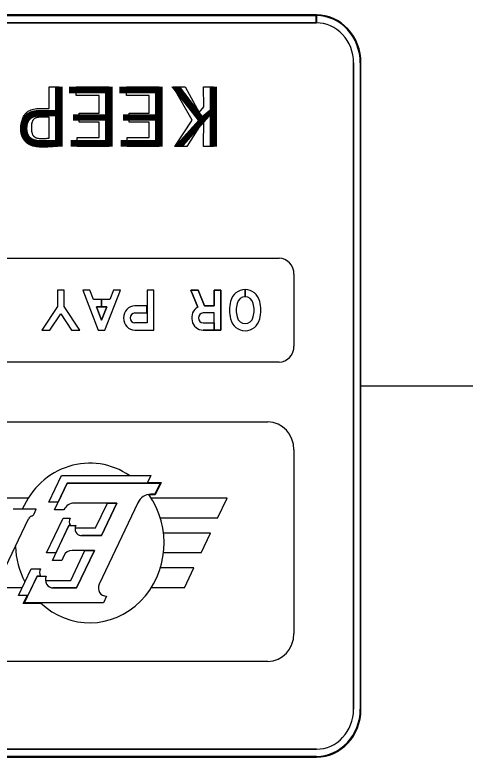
# Model space of a CAD drawing. Extents: x -102643 to -98250, y 54554 to 62384.
# Drawn here: x -101344 to -101029, y 61400 to 61919 of the extents above; entities that cross this region are included whole.
import ezdxf

# ---------------------------------------------------------------- set-up
doc = ezdxf.new("R2010")
doc.units = 0
for name, color, linetype in [('GSBWFill', 7, 'Continuous'), ('GSColorFill', 7, 'Continuous'), ('GSOutline', 7, 'Continuous'), ('LeaderLine_dp', 7, 'Continuous'), ('SignPanel', 7, 'Continuous')]:
    doc.layers.add(name, color=color, linetype=linetype)

msp = doc.modelspace()

# ---------------------------------------------------------------- linework, layer by layer
at = {"layer": 'GSBWFill'}
for p, q in [((-101133.26, 61919), (-101585.67, 61919)), ((-101133.26, 61913.42), (-101133.26, 61919)), ((-101133.21, 61919), (-101133.21, 61913.42)), ((-101585.67, 61913.42), (-101133.26, 61913.42)), ((-101107.2, 61885.49), (-101107.2, 61433.02)), ((-101102, 61433.02), (-101102, 61885.49)), ((-101133.21, 61405.09), (-101585.67, 61405.09)), ((-101585.67, 61399.51), (-101133.21, 61399.51))]:
    msp.add_line(p, q, dxfattribs=at)
for centre, major_axis, start_param, end_param in [((-101133.21, 61885.49), (0, -33.52), 1.570796, 3.141593), ((-101133.21, 61885.49), (0, -27.93), 1.570796, 3.141593), ((-101133.21, 61433.02), (0, -33.52), 0, 1.570796), ((-101133.21, 61433.02), (0, -27.93), 0, 1.570796)]:
    msp.add_ellipse(centre, major_axis=major_axis, ratio=0.931035, start_param=start_param, end_param=end_param, dxfattribs=at)
at = {"layer": 'GSColorFill'}
for p, q in [((-101133.21, 61919), (-101585.67, 61919)), ((-101102, 61433.02), (-101102, 61885.49)), ((-101585.67, 61399.51), (-101133.21, 61399.51))]:
    msp.add_line(p, q, dxfattribs=at)
for centre, start_param, end_param in [((-101133.21, 61885.49), 1.570796, 3.141593), ((-101133.21, 61433.02), 0, 1.570796)]:
    msp.add_ellipse(centre, major_axis=(0, -33.52), ratio=0.931035, start_param=start_param, end_param=end_param, dxfattribs=at)
at = {"layer": 'GSOutline'}
for p, q in [((-101133.21, 61919), (-101585.67, 61919)), ((-101133.21, 61913.42), (-101585.67, 61913.42)), ((-101107.2, 61433.02), (-101107.2, 61885.49)), ((-101102, 61433.02), (-101102, 61885.49)), ((-101585.67, 61405.09), (-101133.21, 61405.09)), ((-101585.67, 61399.51), (-101133.21, 61399.51))]:
    msp.add_line(p, q, dxfattribs=at)
for centre, major_axis, start_param, end_param in [((-101133.21, 61885.49), (0, -33.52), 1.570796, 3.141593), ((-101133.21, 61885.49), (0, -27.93), 1.570796, 3.141593), ((-101133.21, 61433.02), (0, -33.52), 0, 1.570796), ((-101133.21, 61433.02), (0, -27.93), 0, 1.570796)]:
    msp.add_ellipse(centre, major_axis=major_axis, ratio=0.931035, start_param=start_param, end_param=end_param, dxfattribs=at)
at = {"layer": 'LeaderLine_dp'}
msp.add_line((-101102, 61659.26), (-100943.43, 61659.26), dxfattribs=at)
at = {"layer": 'SignPanel'}
for p, q in [((-101133.26, 61919), (-101585.67, 61919)), ((-101133.21, 61919), (-101585.67, 61919)), ((-101133.26, 61913.42), (-101133.26, 61919)), ((-101133.21, 61919), (-101133.21, 61913.42)), ((-101133.21, 61919), (-101133.21, 61918.45)), ((-101133.21, 61918.45), (-101133.21, 61919)), ((-101585.67, 61918.45), (-101133.21, 61918.45)), ((-101585.67, 61913.42), (-101133.26, 61913.42)), ((-101107.2, 61885.49), (-101107.2, 61433.02)), ((-101102.52, 61885.49), (-101102.52, 61433.02)), ((-101102, 61433.02), (-101102, 61885.49)), ((-101102, 61433.02), (-101102, 61885.49)), ((-101559.62, 61748.63), (-101159.26, 61748.63)), ((-101148.86, 61737.46), (-101148.86, 61687.19)), ((-101183.01, 61726.78), (-101183.01, 61721.75)), ((-101183.01, 61726.78), (-101183.01, 61721.75)), ((-101183, 61721.75), (-101183, 61726.78)), ((-101183, 61721.75), (-101183, 61726.78)), ((-101251.65, 61715.4), (-101260.11, 61715.4)), ((-101251.65, 61703.39), (-101260.11, 61703.39)), ((-101251.65, 61703.39), (-101260.11, 61703.39)), ((-101251.65, 61703.39), (-101260.11, 61703.39)), ((-101159.26, 61676.01), (-101559.62, 61676.01)), ((-101551.82, 61634.08), (-101167.06, 61634.08)), ((-101148.86, 61614.53), (-101148.86, 61486.09)), ((-101320.37, 61577.85), (-101311.51, 61596.52)), ((-101311.51, 61596.52), (-101248.95, 61596.52)), ((-101248.95, 61596.52), (-101251.42, 61591.28)), ((-101251.21, 61591.74), (-101241.75, 61591.74)), ((-101241.75, 61591.74), (-101245.87, 61583.05)), ((-101316.29, 61572.62), (-101307.44, 61591.28)), ((-101307.44, 61591.28), (-101313.8, 61577.85)), ((-101307.44, 61591.28), (-101242.45, 61591.28)), ((-101251.42, 61591.28), (-101307.44, 61591.28)), ((-101242.45, 61591.28), (-101246.14, 61583.5)), ((-101246.14, 61583.5), (-101248.86, 61583.5)), ((-101245.87, 61583.05), (-101248.86, 61583.05)), ((-101334.71, 61580.81), (-101494.59, 61580.81)), ((-101313.8, 61577.85), (-101320.37, 61577.85)), ((-101272.75, 61577.31), (-101302.58, 61577.31)), ((-101287.6, 61559.88), (-101279.32, 61577.31)), ((-101258.12, 61577.41), (-101285.1, 61520.55)), ((-101283.52, 61554.63), (-101272.75, 61577.31)), ((-101272.75, 61577.31), (-101283.52, 61554.63)), ((-101279.32, 61577.31), (-101272.75, 61577.31)), ((-101195.66, 61580.81), (-101248.73, 61580.81)), ((-101202.27, 61566.84), (-101195.66, 61580.81)), ((-101329.09, 61572.96), (-101345.34, 61572.96)), ((-101330.55, 61569.88), (-101329.09, 61572.96)), ((-101309.78, 61572.62), (-101316.29, 61572.62)), ((-101350.6, 61532.43), (-101334.5, 61566.35)), ((-101321.91, 61542.41), (-101310.32, 61566.84)), ((-101310.32, 61566.84), (-101305.44, 61566.84)), ((-101202.27, 61566.84), (-101242.33, 61566.84)), ((-101317.82, 61537.17), (-101306.24, 61561.61)), ((-101306.24, 61561.61), (-101315.34, 61542.41)), ((-101306.24, 61561.61), (-101301.34, 61561.61)), ((-101305.21, 61561.61), (-101306.24, 61561.61)), ((-101301.94, 61559.93), (-101287.6, 61559.88)), ((-101207.23, 61556.37), (-101240.13, 61556.37)), ((-101213.85, 61542.41), (-101207.23, 61556.37)), ((-101297.78, 61554.63), (-101283.52, 61554.63)), ((-101283.52, 61554.63), (-101297.17, 61554.67)), ((-101315.34, 61542.41), (-101321.91, 61542.41)), ((-101309.82, 61540.34), (-101311.32, 61537.17)), ((-101304.98, 61523.21), (-101295.05, 61544.15)), ((-101288.48, 61544.15), (-101304.03, 61544.15)), ((-101300.9, 61517.98), (-101288.48, 61544.15)), ((-101288.48, 61544.15), (-101300.9, 61517.98)), ((-101295.05, 61544.15), (-101288.48, 61544.15)), ((-101213.85, 61542.41), (-101240.13, 61542.41)), ((-101311.32, 61537.17), (-101317.82, 61537.17)), ((-101341.5, 61512.74), (-101332.65, 61531.41)), ((-101332.65, 61531.41), (-101326.16, 61531.41)), ((-101218.81, 61531.94), (-101242.33, 61531.94)), ((-101225.43, 61517.98), (-101218.81, 61531.94)), ((-101337.43, 61507.51), (-101328.58, 61526.17)), ((-101328.56, 61526.19), (-101334.94, 61512.74)), ((-101328.58, 61526.17), (-101322.07, 61526.17)), ((-101326.15, 61526.19), (-101328.56, 61526.19)), ((-101322.66, 61523.21), (-101304.98, 61523.21)), ((-101339.02, 61517.98), (-101524.4, 61517.98)), ((-101317.46, 61517.98), (-101300.9, 61517.98)), ((-101300.9, 61517.98), (-101317.46, 61517.98)), ((-101225.43, 61517.98), (-101248.73, 61517.98)), ((-101334.94, 61512.74), (-101341.5, 61512.74)), ((-101338.21, 61506.99), (-101335.49, 61512.74)), ((-101279.96, 61512.19), (-101282.18, 61507.51)), ((-101325.55, 61506.99), (-101338.21, 61506.99)), ((-101282.18, 61507.51), (-101337.43, 61507.51)), ((-101167.06, 61466.54), (-101551.82, 61466.54)), ((-101133.21, 61405.09), (-101585.67, 61405.09)), ((-101133.21, 61400.07), (-101585.67, 61400.07)), ((-101585.67, 61399.51), (-101133.21, 61399.51)), ((-101585.67, 61399.51), (-101133.21, 61399.51))]:
    msp.add_line(p, q, dxfattribs=at)
for points in [[(-101326.81, 61853.46), (-101320.16, 61853.46), (-101320.16, 61868.73), (-101313.15, 61868.73), (-101313.15, 61827.1)], [(-101278.16, 61868.73), (-101278.16, 61826.83), (-101300.48, 61826.83), (-101300.48, 61833.25), (-101285.18, 61833.25), (-101285.18, 61843.79), (-101299.01, 61843.79), (-101299.01, 61850.25), (-101285.18, 61850.25), (-101285.18, 61862.47), (-101301.08, 61862.47), (-101301.08, 61868.73), (-101278.16, 61868.73)], [(-101243.17, 61868.73), (-101243.17, 61826.83), (-101265.5, 61826.83), (-101265.5, 61833.25), (-101250.19, 61833.25), (-101250.19, 61843.79), (-101264.03, 61843.79), (-101264.03, 61850.25), (-101250.19, 61850.25), (-101250.19, 61862.47), (-101266.09, 61862.47), (-101266.09, 61868.73), (-101243.17, 61868.73)], [(-101224.92, 61868.73), (-101215.12, 61850.63), (-101212, 61854.74), (-101212.08, 61868.73), (-101205.06, 61868.73), (-101205.06, 61826.83), (-101212.08, 61826.83), (-101212, 61845.31), (-101212.24, 61845.31), (-101223.75, 61826.83), (-101232.24, 61826.83), (-101220.05, 61845.23), (-101233.41, 61868.73), (-101224.92, 61868.73)], [(-101320.16, 61832.74), (-101320.16, 61847.4), (-101325.59, 61847.4)], [(-101260.11, 61698.36), (-101246.97, 61698.36), (-101246.97, 61726.29), (-101251.65, 61726.29), (-101251.65, 61715.4)], [(-101260.11, 61698.36), (-101246.97, 61698.36), (-101246.97, 61726.29), (-101251.65, 61726.29), (-101251.65, 61703.39)], [(-101260.11, 61698.36), (-101246.97, 61698.36), (-101246.97, 61726.29), (-101251.65, 61726.29), (-101251.65, 61703.39)], [(-101212.48, 61698.36), (-101199.91, 61698.36), (-101199.91, 61726.29), (-101204.59, 61726.29), (-101204.59, 61715.4), (-101211.48, 61715.4), (-101215.87, 61726.29), (-101220.97, 61726.29), (-101216.18, 61714.41)], [(-101216.18, 61714.41), (-101220.97, 61726.29), (-101215.87, 61726.29), (-101211.48, 61715.4), (-101204.59, 61715.4), (-101204.59, 61726.29), (-101199.91, 61726.29), (-101199.91, 61698.36), (-101204.59, 61698.36), (-101204.59, 61710.37), (-101212.48, 61710.37)], [(-101216.18, 61714.41), (-101220.97, 61726.29), (-101215.87, 61726.29), (-101211.48, 61715.4), (-101204.59, 61715.4), (-101204.59, 61726.29), (-101199.91, 61726.29), (-101199.91, 61698.36), (-101204.59, 61698.36), (-101204.59, 61710.37), (-101212.48, 61710.37)], [(-101260.11, 61710.37), (-101251.66, 61710.37), (-101251.66, 61715.4), (-101260.11, 61715.4)], [(-101260.11, 61710.37), (-101251.66, 61710.37), (-101251.66, 61715.4), (-101260.11, 61715.4)], [(-101260.11, 61710.37), (-101251.65, 61710.37), (-101251.65, 61703.39)], [(-101212.48, 61703.39), (-101204.59, 61703.39), (-101204.59, 61710.37), (-101212.48, 61710.37)], [(-101204.59, 61703.39), (-101204.59, 61698.36), (-101212.48, 61698.36)], [(-101212.48, 61703.39), (-101204.59, 61703.39)], [(-101204.59, 61703.39), (-101204.59, 61698.36), (-101212.48, 61698.36)], [(-101212.48, 61703.39), (-101204.59, 61703.39)]]:
    msp.add_lwpolyline(points, dxfattribs=at)
for points in [[(-101314.32, 61714.98), (-101325.24, 61698.36), (-101319.52, 61698.36), (-101311.98, 61709.82), (-101304.45, 61698.36), (-101298.72, 61698.36), (-101309.64, 61714.98), (-101309.64, 61726.29), (-101314.32, 61726.29)], [(-101314.32, 61714.98), (-101325.24, 61698.36), (-101319.52, 61698.36), (-101311.98, 61709.82), (-101304.45, 61698.36), (-101298.72, 61698.36), (-101309.64, 61714.98), (-101309.64, 61726.29), (-101314.32, 61726.29)], [(-101314.32, 61714.98), (-101325.24, 61698.36), (-101319.52, 61698.36), (-101311.98, 61709.82), (-101304.45, 61698.36), (-101298.72, 61698.36), (-101309.64, 61714.98), (-101309.64, 61726.29), (-101314.32, 61726.29)], [(-101277.76, 61719.72), (-101289, 61719.72), (-101291.56, 61726.29), (-101296.64, 61726.29), (-101285.72, 61698.36), (-101281.04, 61698.36), (-101270.12, 61726.29), (-101275.19, 61726.29)], [(-101287.03, 61714.7), (-101283.38, 61714.7), (-101283.38, 61719.72), (-101289, 61719.72), (-101291.56, 61726.29), (-101296.64, 61726.29), (-101285.72, 61698.36), (-101281.04, 61698.36), (-101270.12, 61726.29), (-101275.19, 61726.29), (-101277.76, 61719.72), (-101283.38, 61719.72), (-101283.38, 61714.7), (-101279.73, 61714.7), (-101283.38, 61705.36)], [(-101287.03, 61714.7), (-101283.38, 61714.7), (-101283.38, 61719.72), (-101289, 61719.72), (-101291.56, 61726.29), (-101296.64, 61726.29), (-101285.72, 61698.36), (-101281.04, 61698.36), (-101270.12, 61726.29), (-101275.19, 61726.29), (-101277.76, 61719.72), (-101283.38, 61719.72), (-101283.38, 61714.7), (-101279.73, 61714.7), (-101283.38, 61705.36)], [(-101287.03, 61714.7), (-101283.38, 61705.36), (-101279.73, 61714.7)]]:
    msp.add_lwpolyline(points, close=True, dxfattribs=at)
for centre, major_axis, start_param, end_param in [((-101133.21, 61885.49), (0, -33.52), 1.570796, 3.141593), ((-101133.21, 61885.49), (0, -33.52), 1.570796, 3.141593), ((-101133.21, 61885.49), (0, -32.96), 1.570796, 3.141593), ((-101133.21, 61885.49), (0, -27.93), 1.570796, 3.141593), ((-101159.26, 61737.46), (0, 11.17), 4.712389, 6.283185), ((-101183, 61715.46), (0, -11.32), 1.831929, 4.451257), ((-101183, 61715.46), (0, -11.32), 3.141716, 4.451257), ((-101183, 61715.46), (0, -11.32), 3.141716, 4.451257), ((-101183, 61715.46), (0, -11.32), 1.831929, 3.141593), ((-101183, 61715.46), (0, -11.32), 1.831929, 3.141593), ((-101183, 61715.46), (0, -6.29), 1.831929, 4.451257), ((-101183, 61715.46), (0, -6.29), 3.141815, 4.451257), ((-101183, 61715.46), (0, -6.29), 3.141815, 4.451257), ((-101183, 61715.46), (0, -6.29), 1.831929, 3.141593), ((-101183, 61715.46), (0, -6.29), 1.831929, 3.141593), ((-101172.08, 61712.32), (0, -23.46), 4.451257, 4.973521), ((-101172.08, 61712.32), (0, -23.46), 4.451257, 4.973521), ((-101172.08, 61712.32), (0, -23.46), 4.451257, 4.973521), ((-101172.08, 61712.32), (0, -18.43), 4.451257, 4.973521), ((-101172.08, 61712.32), (0, -18.43), 4.451257, 4.973521), ((-101172.08, 61712.32), (0, -18.43), 4.451257, 4.973521), ((-101193.93, 61712.32), (0, -18.43), 1.309664, 1.831929), ((-101193.93, 61712.32), (0, -18.43), 1.309664, 1.831929), ((-101193.93, 61712.32), (0, -18.43), 1.309664, 1.831929), ((-101193.93, 61712.32), (0, -23.46), 1.309664, 1.831929), ((-101193.93, 61712.32), (0, -23.46), 1.309664, 1.831929), ((-101193.93, 61712.32), (0, -23.46), 1.309664, 1.831929), ((-101260.11, 61706.88), (0, -8.52), 3.141593, 6.283185), ((-101260.11, 61706.88), (0, -8.52), 3.141593, 6.283185), ((-101260.11, 61706.88), (0, -8.52), 3.141593, 6.283185), ((-101212.48, 61706.88), (0, -8.52), 3.62744, 6.283185), ((-101212.48, 61706.88), (0, -8.52), 3.62744, 6.283185), ((-101212.48, 61706.88), (0, -8.52), 3.62744, 6.283185), ((-101260.11, 61706.88), (0, -3.49), 3.141593, 6.283185), ((-101260.11, 61706.88), (0, -3.49), 3.141593, 6.283185), ((-101260.11, 61706.88), (0, -3.49), 3.141593, 6.283185), ((-101212.48, 61706.88), (0, -3.49), 3.141593, 6.283185), ((-101212.48, 61706.88), (0, -3.49), 3.141593, 6.283185), ((-101212.48, 61706.88), (0, -3.49), 3.141593, 6.283185), ((-101183, 61709.19), (0, -11.32), 4.973521, 7.592849), ((-101183, 61709.19), (0, -11.32), 4.973521, 7.592849), ((-101183, 61709.19), (0, -11.32), 4.973521, 7.592849), ((-101183, 61709.19), (0, -6.29), 4.973521, 7.592849), ((-101183, 61709.19), (0, -6.29), 4.973521, 7.592849), ((-101183, 61709.19), (0, -6.29), 4.973521, 7.592849), ((-101159.26, 61687.19), (0, 11.17), 3.141593, 4.712389), ((-101167.06, 61614.53), (0, 19.55), 4.712389, 6.283185), ((-101291.72, 61549.4), (0, -55.85), 2.575028, 4.276877), ((-101291.72, 61549.4), (0, -55.85), 5.560451, 8.508004), ((-101248.86, 61572.34), (0, 11.17), 6.283185, 7.382728), ((-101248.86, 61572.34), (0, 10.72), 6.283185, 6.414151), ((-101302.58, 61568.59), (0, 8.73), 0, 1.090998), ((-101331.61, 61564.77), (0, 3.49), 0.286787, 1.099486), ((-101333.45, 61571.46), (0, 3.49), 3.428379, 4.240701), ((-101301.88, 61564.41), (0, -4.54), 4.143779, 5.375263), ((-101297.78, 61559.17), (0, -4.54), 4.143779, 6.283185), ((-101297.78, 61559.17), (0, -4.54), 4.543968, 6.428647), ((-101291.72, 61549.4), (0, -55.85), 4.754688, 5.22337), ((-101304.03, 61537.18), (0, 6.98), 0, 1.099353), ((-101321.55, 61528.8), (0, -5.58), 4.227342, 5.199557), ((-101317.47, 61523.57), (0, -5.58), 4.227342, 6.283185), ((-101317.47, 61523.57), (0, -5.58), 4.77493, 6.283185), ((-101280.31, 61517.94), (0, -5.76), 4.241147, 6.349586), ((-101167.06, 61486.09), (0, 19.55), 3.141593, 4.712389), ((-101133.21, 61433.02), (0, -33.52), 0, 1.570796), ((-101133.21, 61433.02), (0, -27.93), 0, 1.570796), ((-101133.21, 61433.02), (0, -33.52), 0, 1.570796), ((-101133.21, 61433.02), (0, -32.96), 0, 1.570796)]:
    msp.add_ellipse(centre, major_axis=major_axis, ratio=0.931035, start_param=start_param, end_param=end_param, dxfattribs=at)
for points in [[(-101339.64, 61839.78), (-101339.63, 61840.31), (-101339.61, 61841.83), (-101339.33, 61844.01), (-101338.79, 61846.02), (-101338.22, 61847.41), (-101337.65, 61848.49), (-101337.09, 61849.32), (-101336.59, 61849.93), (-101336.06, 61850.5), (-101335.32, 61851.15), (-101334.32, 61851.82), (-101333, 61852.47), (-101331.04, 61853.1), (-101328.87, 61853.42), (-101327.35, 61853.45), (-101326.81, 61853.46)], [(-101325.59, 61847.4), (-101326.12, 61847.39), (-101326.9, 61847.37), (-101327.9, 61847.25), (-101328.48, 61847.16), (-101329.01, 61847.03), (-101329.5, 61846.86), (-101330.05, 61846.59), (-101330.46, 61846.3), (-101330.76, 61846.04), (-101331.05, 61845.75), (-101331.37, 61845.33), (-101331.7, 61844.76), (-101331.92, 61844.22), (-101332.11, 61843.62), (-101332.34, 61842.6), (-101332.47, 61841.3), (-101332.48, 61840.28), (-101332.49, 61839.9)], [(-101325.23, 61826.43), (-101325.74, 61826.43), (-101327.21, 61826.46), (-101329.14, 61826.68), (-101330.98, 61827.05), (-101332.06, 61827.37), (-101333.07, 61827.76), (-101334.02, 61828.21), (-101334.91, 61828.77), (-101335.57, 61829.27), (-101336.2, 61829.8), (-101336.92, 61830.56), (-101337.68, 61831.6), (-101338.21, 61832.57), (-101338.58, 61833.4), (-101338.92, 61834.3), (-101339.33, 61835.8), (-101339.6, 61837.73), (-101339.63, 61839.17), (-101339.64, 61839.78)], [(-101332.49, 61839.9), (-101332.48, 61839.56), (-101332.47, 61838.63), (-101332.35, 61837.45), (-101332.16, 61836.5), (-101331.99, 61835.92), (-101331.79, 61835.39), (-101331.49, 61834.8), (-101331.19, 61834.37), (-101330.92, 61834.07), (-101330.63, 61833.78), (-101330.22, 61833.46), (-101329.67, 61833.15), (-101329.17, 61832.94), (-101328.62, 61832.77), (-101327.74, 61832.57), (-101326.64, 61832.45), (-101325.78, 61832.44), (-101325.47, 61832.43)], [(-101325.47, 61832.43), (-101325.06, 61832.44), (-101324.22, 61832.45), (-101322.93, 61832.52), (-101321.58, 61832.62), (-101320.65, 61832.7), (-101320.16, 61832.74)], [(-101313.15, 61827.1), (-101314.05, 61827), (-101315.93, 61826.81), (-101318.86, 61826.6), (-101321.99, 61826.45), (-101324.13, 61826.44), (-101325.23, 61826.43)]]:
    msp.add_open_spline(points, degree=3, dxfattribs=at)

# ---------------------------------------------------------------- texts
for s, p in [('P', (-101306.13, 61868.73)), ('P', (-101306.13, 61868.73)), ('E', (-101271.15, 61868.73)), ('E', (-101271.15, 61868.73)), ('E', (-101236.16, 61868.73)), ('E', (-101236.16, 61868.73)), ('K', (-101198.05, 61868.73)), ('K', (-101198.05, 61868.73))]:
    msp.add_text(s, height=41.89, rotation=180, dxfattribs=at).set_placement(p)

doc.saveas('drawing.dxf')
